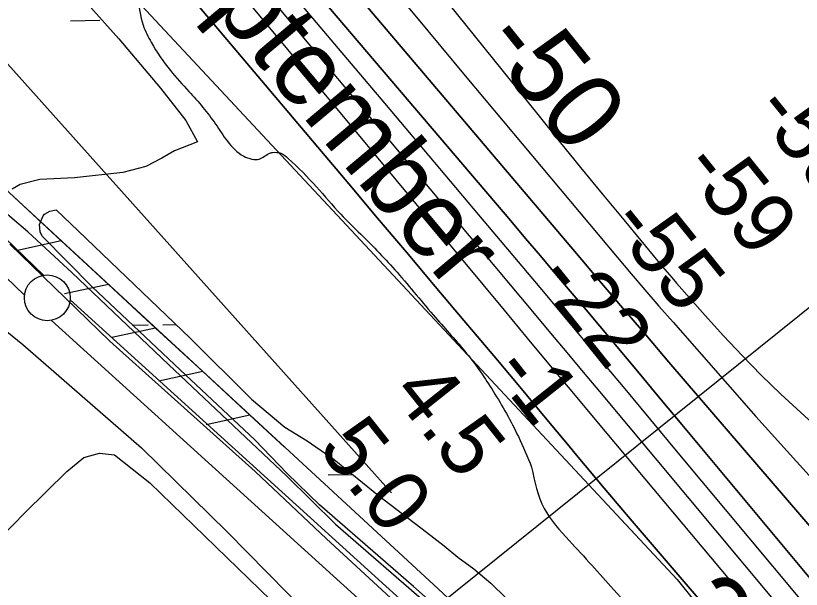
# Model space of a CAD drawing. Extents: x 3767014 to 3805179, y 361544 to 387384.
# Drawn here: x 3778084 to 3778940, y 382515 to 383140 of the extents above; entities that cross this region are included whole.
import ezdxf

# ---------------------------------------------------------------- set-up
doc = ezdxf.new("R2010")
doc.units = 0
for name, color, linetype in [('V-FLOD-BASE', 7, 'Continuous'), ('V-LEVE-TOET', 7, 'Continuous'), ('V-RIVR-EDGE', 7, 'Continuous'), ('V-RIVR-IDEN', 7, 'Continuous'), ('V-RIVR-RANG', 7, 'Continuous'), ('V-ROAD-CNTR', 7, 'Continuous'), ('V-RRAP-FSHR', 7, 'Continuous'), ('V-SITE-VEGE', 7, 'Continuous'), ('V-SURV-LINE', 7, 'Continuous'), ('V-TOPO-DPTH', 7, 'Continuous'), ('V-TOPO-MAJR', 7, 'Continuous'), ('V-TOPO-MAJR-IDEN', 7, 'Continuous'), ('V-TOPO-MINR', 7, 'Continuous'), ('V-TOPO-WATR', 7, 'Continuous'), ('V-WETL-SWMP', 7, 'Continuous')]:
    doc.layers.add(name, color=color, linetype=linetype)

msp = doc.modelspace()

# ---------------------------------------------------------------- linework, layer by layer
at = {"layer": 'V-FLOD-BASE'}
for points in [[(3778077.741, 382890.782), (3778186.756, 382785.16), (3778246.473, 382731.277)], [(3778692.098, 382328.079), (3778643.187, 382372.197), (3778588.09, 382420.374), (3778515.771, 382484.163), (3778422.761, 382569.696), (3778344.896, 382643.025), (3778246.473, 382731.277)]]:
    msp.add_lwpolyline(points, dxfattribs=at)
at = {"layer": 'V-LEVE-TOET'}
for points in [[(3778250.643, 382759.624), (3778145.759, 382859.539), (3778097.149, 382904.364), (3778080.063, 382918.624), (3778064.267, 382932.227), (3777948.815, 383043.517), (3777778.188, 383213.378), (3777627.559, 383359.319), (3777462.353, 383514.84), (3777284.081, 383693.815), (3777144.463, 383837.042), (3777009.432, 383982.073), (3776900.155, 384104.426), (3776770.729, 384259.935), (3776630.773, 384424.51), (3776502.622, 384572.538), (3776386.199, 384708.629), (3776267.407, 384848.723), (3776139.229, 384998.481), (3776021.579, 385139.17), (3775958.368, 385214.876)], [(3776800.942, 384059.618), (3776917.198, 383933.912), (3777056.954, 383782.03), (3777197.989, 383622.088), (3777340.366, 383486.983), (3777477.99, 383360.462), (3777641.365, 383211.261), (3777790.195, 383069.332), (3777927.911, 382937.04), (3778011.109, 382858.134), (3778016.915, 382847.329), (3778035.705, 382826.849), (3778091.825, 382781.568), (3778221.152, 382668.764), (3778314.358, 382577.321)], [(3778250.643, 382759.624), (3778379.499, 382638.087), (3778432.575, 382585.789), (3778534.504, 382496.902), (3778675.011, 382372.713), (3778703.947, 382346.241), (3778725.994, 382325.876)], [(3778314.358, 382577.321), (3778401.918, 382488.327), (3778454.988, 382436.713), (3778531.485, 382363.374), (3778603.096, 382303.001)]]:
    msp.add_lwpolyline(points, dxfattribs=at)
at = {"layer": 'V-RIVR-EDGE'}
for points in [[(3776564.722, 385223.299), (3776600.731, 385181.098), (3776661.2, 385105.736), (3776715.203, 385032.007), (3776816.784, 384902.358), (3776846.605, 384861.038), (3776857.883, 384843.218), (3776882.888, 384816.468), (3776915.962, 384782.419), (3776954.66, 384732.99), (3776978.836, 384698.155), (3777017.529, 384647.108), (3777120.713, 384511.794), (3777150.55, 384476.944), (3777181.198, 384442.901), (3777207.8, 384408.06), (3777254.587, 384359.42), (3777285.235, 384325.377), (3777306.975, 384286.503), (3777352.136, 384234.632), (3777398.919, 384184.375), (3777453.759, 384121.966), (3777499.732, 384071.711), (3777554.576, 384010.92), (3777589.252, 383970.397), (3777621.507, 383932.306), (3777678.778, 383871.509), (3777722.335, 383825.304), (3777756.204, 383785.592), (3777794.915, 383741.824), (3777871.521, 383651.056), (3777927.937, 383571.66), (3777966.622, 383517.378), (3777996.431, 383471.207), (3778029.475, 383425.027), (3778067.358, 383373.174), (3778126.177, 383284.876), (3778156.015, 383250.026), (3778180.211, 383223.278), (3778202.787, 383195.725), (3778212.458, 383181.952), (3778217.257, 383160.105), (3778222.842, 383129.359), (3778231.692, 383110.736), (3778252.643, 383079.952), (3778272.805, 383057.257), (3778301.832, 383021.601), (3778314.725, 383002.968), (3778332.478, 382986.749), (3778341.366, 382983.492), (3778349.453, 382983.472), (3778360.791, 382989.914), (3778364.028, 382990.715), (3778372.922, 382989.884), (3778380.996, 382984.203), (3778411.652, 382953.395), (3778438.266, 382923.406), (3778460.048, 382901.516), (3778499.574, 382860.173), (3778541.506, 382810.736), (3778575.377, 382771.833), (3778604.389, 382730.515), (3778631.764, 382681.114), (3778646.24, 382647.92)], [(3778646.24, 382647.92), (3778659.876, 382602.597), (3778687.287, 382567.754), (3778735.679, 382514.257), (3778796.164, 382445.365), (3778835.674, 382397.551), (3778888.899, 382335.956), (3778952.607, 382262.203), (3779012.275, 382190.077), (3779057.436, 382138.206), (3779100.988, 382089.574), (3779134.849, 382046.627), (3779162.264, 382013.401), (3779205.838, 381973.665), (3779260.7, 381920.153), (3779294.566, 381879.632), (3779325.194, 381837.502), (3779360.663, 381790.507), (3779412.312, 381745.899), (3779454.294, 381716.68), (3779488.994, 381685.863), (3779533.368, 381642.89), (3779576.119, 381597.495), (3779620.485, 381551.287), (3779676.969, 381499.388), (3779726.99, 381450.74), (3779776.179, 381392.389), (3779876.993, 381279.725), (3779935.05, 381210.029), (3779960.041, 381177.618), (3780000.375, 381136.273), (3780060.096, 381085.174), (3780089.114, 381046.283), (3780155.269, 380980.612), (3780221.433, 380918.984), (3780269.028, 380870.342), (3780345.672, 380794.939), (3780399.741, 380747.899), (3780525.62, 380632.747), (3780574.841, 380587.335), (3780617.604, 380546.793), (3780649.066, 380515.174), (3780673.232, 380476.295), (3780710.32, 380430.105), (3780715.929, 380409.064), (3780730.431, 380386.383), (3780746.557, 380366.934), (3780778.851, 380344.209), (3780832.137, 380307.684), (3780871.695, 380279.28), (3780938.666, 380216.842), (3780975.778, 380180.357), (3781018.547, 380142.24), (3781081.494, 380087.899), (3781142.025, 380037.607), (3781200.156, 379997.835), (3781279.276, 379942.646), (3781347.092, 379894.762), (3781401.179, 379855), (3781466.567, 379806.314), (3781540.856, 379760.032), (3781563.475, 379749.463), (3781591.761, 379741.305), (3781611.132, 379725.891), (3781641.814, 379705.597), (3781703.987, 379665.006), (3781768.578, 379621.175), (3781821.047, 379581.417), (3781840.409, 379561.959), (3781862.209, 379547.348), (3781884.029, 379540.824), (3781913.115, 379529.43), (3781965.635, 379509.89), (3782018.949, 379484.687), (3782023.776, 379474.162), (3782024.562, 379465.264), (3782031.018, 379459.587), (3782040.723, 379459.563), (3782056.888, 379455.479), (3782096.48, 379440.824), (3782142.534, 379422.918), (3782192.615, 379398.532), (3782256.437, 379370.877), (3782308.124, 379341.634), (3782355.768, 379312.402), (3782425.225, 379274.219), (3782483.37, 379240.108), (3782518.081, 379214.143), (3782612.541, 379148.401), (3782677.126, 379102.144), (3782722.345, 379073.726), (3782774.821, 379036.394), (3782813.562, 379004.757), (3782852.3, 378971.503), (3782891.856, 378942.291), (3782929.816, 378921.979), (3782948.387, 378909.802), (3782956.456, 378902.503), (3782965.324, 378891.159), (3782976.623, 378881.426), (3783009.747, 378867.595), (3783020.246, 378861.908), (3783062.243, 378838.351), (3783100.998, 378812.375), (3783151.876, 378783.135), (3783202.741, 378748.233), (3783247.956, 378718.198), (3783325.482, 378672.717), (3783407.843, 378619.945), (3783473.245, 378576.92), (3783515.225, 378546.893), (3783550.759, 378526.587), (3783593.566, 378503.836), (3783636.355, 378473.807), (3783701.749, 378427.547), (3783745.35, 378399.134), (3783781.695, 378379.634), (3783840.643, 378343.095), (3783916.53, 378288.722), (3783971.442, 378255.428), (3784058.669, 378208.305), (3784177.383, 378139.269), (3784249.255, 378096.228), (3784300.952, 378071.029), (3784367.999, 378039.322), (3784407.569, 378015.771), (3784474.592, 377974.36), (3784555.345, 377925.636), (3784594.113, 377904.513), (3784636.123, 377886.616), (3784690.236, 377857.368), (3784719.292, 377833.843), (3784772.601, 377806.214), (3784811.368, 377785.091), (3784863.85, 377750.185), (3784995.456, 377661.707), (3785050.364, 377626.795), (3785102.863, 377599.168), (3785153.772, 377582.059), (3785203.053, 377560.91), (3785266.865, 377529.211)]]:
    msp.add_spline(points, degree=3, dxfattribs=at)
at = {"layer": 'V-RIVR-RANG'}
msp.add_line((3778518.464, 382476.514), (3779220.036, 383040.248), dxfattribs=at)
at = {"layer": 'V-ROAD-CNTR'}
msp.add_arc((3779253.341, 383526.65), 1823.751, 212.363325, 236.331483, dxfattribs=at)
at = {"layer": 'V-RRAP-FSHR'}
for p, q in [((3778133.64, 382894.426), (3778085.925, 382884.046)), ((3778185.06, 382846.931), (3778137.346, 382836.551)), ((3778236.481, 382799.436), (3778188.766, 382789.056)), ((3778287.902, 382751.941), (3778240.187, 382741.561)), ((3778339.322, 382704.446), (3778291.608, 382694.066))]:
    msp.add_line(p, q, dxfattribs=at)
for points in [[(3782184.756, 379271.949), (3781634.784, 379600.702), (3781303.145, 379780.78), (3781133.821, 379909.411), (3780890.404, 380113.256), (3780565.67, 380378.863), (3780204.676, 380695.617), (3779970.329, 380928.932), (3779684.372, 381135.741), (3779561.421, 381256.633), (3779323.818, 381551.992), (3779094.739, 381872.997), (3778954.725, 382074.421), (3778782.34, 382292.407), (3778544.366, 382515.056), (3778048.414, 382973.145), (3777558.565, 383445.969), (3777072.653, 383926.093), (3776661.747, 384415.936), (3776254.152, 384895.528), (3775977.183, 385214.815)], [(3777068.879, 384385.699), (3778804.838, 382525.57), (3779492.47, 381669.823), (3779587.876, 381548.643), (3779796.903, 381343.309), (3779998.867, 381129.354), (3780179.181, 380943.203), (3780223.637, 380900.07), (3780597.798, 380548.597), (3780675.78, 380460.512), (3780749.105, 380378.076), (3780977.321, 380170.04), (3781125.621, 380046.136), (3781247.143, 379955.707), (3781372.841, 379865.857), (3781588.295, 379714.948), (3781871.171, 379550.27), (3782261.845, 379357.404), (3782506.653, 379202.456), (3782967.84, 378875.243), (3783363.457, 378614.539), (3783723.393, 378389.37)], [(3778133.64, 382894.426), (3778082.218, 382941.921)], [(3778236.481, 382799.436), (3778185.06, 382846.931), (3778133.639, 382894.426)], [(3778287.902, 382751.941), (3778236.48, 382799.436)], [(3778376.619, 382669.997), (3778339.322, 382704.446), (3778287.901, 382751.941)]]:
    msp.add_lwpolyline(points, dxfattribs=at)
at = {"layer": 'V-SITE-VEGE'}
msp.add_lwpolyline([(3778306.017, 382279.906), (3778175.401, 382112.937), (3778168.825, 382109.06), (3778157.598, 382111.755), (3777933.645, 382316.61), (3777925.885, 382330.922), (3777920.837, 382345.235), (3777914.234, 382364.968), (3777912.276, 382383.154), (3777919.993, 382403.677), (3777972.93, 382474.181), (3778094.471, 382598.452), (3778139.936, 382643.033), (3778158.163, 382658.325), (3778175.399, 382663.216), (3778191.591, 382661.164), (3778230.165, 382630.608), (3778386.067, 382479.557), (3778399.014, 382463.604), (3778402.715, 382448.655), (3778397.419, 382418.562), (3778367.082, 382366.141)], close=True, dxfattribs=at)
at = {"layer": 'V-SURV-LINE'}
for points in [[(3777377.157, 383568.76), (3778114.52, 382856.998)], [(3778093.693, 382835.405), (3777356.329, 383547.168)], [(3778143.366, 382830.007), (3778702.45, 382322.94)], [(3778682.288, 382300.726), (3778123.204, 382807.792)]]:
    msp.add_lwpolyline(points, dxfattribs=at)
msp.add_circle((3778118.48, 382832.327), 25, dxfattribs=at)
at = {"layer": 'V-TOPO-DPTH'}
for points in [[(3779101.046, 382406.885), (3778795.842, 382762.398), (3778770.574, 382791.888), (3778745.344, 382821.409), (3778720.17, 382850.979), (3778695.034, 382880.581), (3778321.003, 383321.918), (3778305.202, 383340.568), (3778289.403, 383359.22), (3778273.61, 383377.877), (3778257.82, 383396.537), (3778228.189, 383431.562), (3778227.219, 383432.713), (3778226.251, 383433.866), (3778225.287, 383435.022), (3778224.326, 383436.18), (3778186.457, 383481.98), (3778166.579, 383506.054), (3778146.725, 383530.147), (3778126.903, 383554.267), (3778107.105, 383578.405), (3777658.425, 384126.202)], [(3779101.046, 382406.885), (3778795.842, 382762.398), (3778770.574, 382791.888), (3778745.344, 382821.409), (3778720.17, 382850.979), (3778695.034, 382880.581), (3778321.003, 383321.918), (3778305.202, 383340.568), (3778289.403, 383359.22), (3778273.61, 383377.877), (3778257.82, 383396.537), (3778228.189, 383431.562), (3778227.219, 383432.713), (3778226.251, 383433.866), (3778225.287, 383435.022), (3778224.326, 383436.18), (3778186.457, 383481.98), (3778166.579, 383506.054), (3778146.725, 383530.147), (3778126.903, 383554.267), (3778107.105, 383578.405), (3777658.425, 384126.202)], [(3777617.591, 384049.155), (3777918.651, 383687.627), (3777960.381, 383637.574), (3778002.149, 383587.552), (3778043.975, 383537.578), (3778085.838, 383487.637), (3778120.766, 383446.017), (3778145.196, 383416.91), (3778169.627, 383387.804), (3778194.06, 383358.7), (3778218.495, 383329.598), (3778248.763, 383293.552), (3778288.317, 383246.414), (3778327.849, 383199.258), (3778367.35, 383152.075), (3778406.829, 383104.875), (3778648.871, 382815.29), (3778666.673, 382793.993), (3778684.475, 382772.695), (3778702.279, 382751.399), (3778720.082, 382730.103), (3778909.421, 382503.635)], [(3777617.591, 384049.155), (3777918.651, 383687.627), (3777960.381, 383637.574), (3778002.149, 383587.552), (3778043.975, 383537.578), (3778085.838, 383487.637), (3778120.766, 383446.017), (3778145.196, 383416.91), (3778169.627, 383387.804), (3778194.06, 383358.7), (3778218.495, 383329.598), (3778248.763, 383293.552), (3778288.317, 383246.414), (3778327.849, 383199.258), (3778367.35, 383152.075), (3778406.829, 383104.875), (3778648.871, 382815.29), (3778666.673, 382793.993), (3778684.475, 382772.695), (3778702.279, 382751.399), (3778720.082, 382730.103), (3778909.421, 382503.635)], [(3777813.681, 384002.604), (3777882.309, 383919.181), (3777950.792, 383835.638), (3778019.056, 383751.917), (3778087.174, 383668.076), (3778216.769, 383508.144), (3778236.811, 383483.45), (3778256.879, 383458.777), (3778276.987, 383434.137), (3778297.121, 383409.518), (3778362.065, 383330.233), (3778414.791, 383266.071), (3778467.65, 383202.019), (3778520.71, 383138.134), (3778573.904, 383074.359), (3778739.468, 382876.495), (3778754.517, 382858.646), (3778769.656, 382840.874), (3778784.928, 382823.217), (3778800.289, 382805.636), (3778890.59, 382703.067), (3778951.86, 382634.911), (3779014.051, 382567.625), (3779077.624, 382501.642)], [(3777813.681, 384002.604), (3777882.309, 383919.181), (3777950.792, 383835.638), (3778019.056, 383751.917), (3778087.174, 383668.076), (3778216.769, 383508.144), (3778236.811, 383483.45), (3778256.879, 383458.777), (3778276.987, 383434.137), (3778297.121, 383409.518), (3778362.065, 383330.233), (3778414.791, 383266.071), (3778467.65, 383202.019), (3778520.71, 383138.134), (3778573.904, 383074.359), (3778739.468, 382876.495), (3778754.517, 382858.646), (3778769.656, 382840.874), (3778784.928, 382823.217), (3778800.289, 382805.636), (3778890.59, 382703.067), (3778951.86, 382634.911), (3779014.051, 382567.625), (3779077.624, 382501.642)], [(3779309.16, 382094.881), (3778809.915, 382694.298), (3778795.025, 382712.178), (3778780.136, 382730.06), (3778765.249, 382747.943), (3778750.364, 382765.828), (3778735.454, 382783.692), (3778720.511, 382801.528), (3778705.516, 382819.32), (3778690.488, 382837.085), (3778688.217, 382839.761), (3778672.024, 382858.838), (3778655.827, 382877.912), (3778639.622, 382896.979), (3778623.412, 382916.043), (3778223.977, 383385.607), (3778212.332, 383399.339), (3778200.715, 383413.095), (3778189.139, 383426.886), (3778177.592, 383440.701), (3777800.934, 383892.722), (3777769.55, 383930.457), (3777738.213, 383968.231)], [(3777738.213, 383968.231), (3777769.55, 383930.457), (3777800.934, 383892.722), (3778177.592, 383440.701), (3778189.139, 383426.886), (3778200.715, 383413.095), (3778212.332, 383399.339), (3778223.977, 383385.607), (3778623.412, 382916.043), (3778639.622, 382896.979), (3778655.827, 382877.912), (3778672.024, 382858.838), (3778688.217, 382839.761), (3778690.488, 382837.085), (3778705.516, 382819.32), (3778720.511, 382801.528), (3778735.454, 382783.692), (3778750.364, 382765.828), (3778765.249, 382747.943), (3778780.136, 382730.06), (3778795.025, 382712.178), (3778809.915, 382694.298), (3779309.16, 382094.881)], [(3779236.017, 382030.277), (3778816.638, 382517.638), (3778786.088, 382553.314), (3778755.654, 382589.088), (3778725.394, 382625.009), (3778695.25, 382661.028), (3778687.159, 382670.743), (3778661.12, 382701.956), (3778635.047, 382733.139), (3778608.922, 382764.279), (3778582.761, 382795.389), (3778572.456, 382807.623), (3778541.109, 382844.823), (3778509.753, 382882.014), (3778478.382, 382919.193), (3778447.002, 382956.365), (3778145.465, 383313.415)]]:
    msp.add_lwpolyline(points, dxfattribs=at)
at = {"layer": 'V-TOPO-MAJR'}
msp.add_lwpolyline([(3778302.779, 383466.781), (3778652.939, 383031.937), (3778676.214, 383003.147), (3778699.563, 382974.418), (3778723.024, 382945.779), (3778746.559, 382917.201), (3778783.822, 382872.13), (3778788.808, 382866.156), (3778793.831, 382860.214), (3778798.909, 382854.318), (3778804.023, 382848.454), (3778835.195, 382813.046), (3778855.14, 382790.996), (3778875.468, 382769.314), (3778896.371, 382748.187), (3778917.658, 382727.428), (3778939.473, 382707.222), (3779421.519, 382267.07)], dxfattribs=at)
at = {"layer": 'V-TOPO-MINR'}
for points in [[(3777658.425, 384126.202), (3778107.105, 383578.405), (3778126.903, 383554.267), (3778146.725, 383530.147), (3778166.579, 383506.054), (3778186.457, 383481.98), (3778224.326, 383436.18), (3778225.287, 383435.022), (3778226.251, 383433.866), (3778227.219, 383432.713), (3778228.189, 383431.562), (3778257.82, 383396.537), (3778273.61, 383377.877), (3778289.403, 383359.22), (3778305.202, 383340.568), (3778321.003, 383321.918), (3778695.034, 382880.581), (3778720.17, 382850.979), (3778745.344, 382821.409), (3778770.574, 382791.888), (3778795.842, 382762.398), (3779101.046, 382406.885)], [(3777036.49, 384114.005), (3777259.111, 383885.577), (3777271.61, 383872.92), (3777284.218, 383860.373), (3777296.99, 383847.994), (3777309.871, 383835.726), (3777453.331, 383700.877), (3777496.647, 383660.865), (3777540.416, 383621.363), (3777584.864, 383582.627), (3777629.766, 383544.402), (3777674.307, 383505.815), (3777717.916, 383466.237), (3777760.129, 383425.172), (3777801.41, 383383.115), (3777922.903, 383254.971), (3777940.978, 383235.743), (3777958.943, 383216.412), (3777976.743, 383196.929), (3777994.432, 383177.344), (3778493.58, 382619.94), (3778493.58, 382619.94)], [(3777617.591, 384049.155), (3777918.651, 383687.627), (3777960.381, 383637.574), (3778002.149, 383587.552), (3778043.975, 383537.578), (3778085.838, 383487.637), (3778120.766, 383446.017), (3778145.196, 383416.91), (3778169.627, 383387.804), (3778194.06, 383358.7), (3778218.495, 383329.598), (3778248.763, 383293.552), (3778288.317, 383246.414), (3778327.849, 383199.258), (3778367.35, 383152.075), (3778406.829, 383104.875), (3778648.871, 382815.29), (3778666.673, 382793.993), (3778684.475, 382772.695), (3778702.279, 382751.399), (3778720.082, 382730.103), (3778909.421, 382503.635)], [(3777614.536, 384017.906), (3778112.899, 383424.18), (3778119.761, 383416.009), (3778126.626, 383407.839), (3778133.495, 383399.673), (3778140.366, 383391.509), (3778151.537, 383378.244), (3778152.824, 383376.713), (3778154.11, 383375.181), (3778155.393, 383373.648), (3778156.676, 383372.113), (3778166.881, 383359.889), (3778173.262, 383352.239), (3778179.638, 383344.585), (3778186.009, 383336.926), (3778192.375, 383329.264), (3778616.181, 382818.754), (3778641.318, 382788.516), (3778666.484, 382758.301), (3778691.69, 382728.12), (3778716.925, 382697.962), (3779102.687, 382237.579)], [(3777813.681, 384002.604), (3777882.309, 383919.181), (3777950.792, 383835.638), (3778019.056, 383751.917), (3778087.174, 383668.076), (3778216.769, 383508.144), (3778236.811, 383483.45), (3778256.879, 383458.777), (3778276.987, 383434.137), (3778297.121, 383409.518), (3778362.065, 383330.233), (3778414.791, 383266.071), (3778467.65, 383202.019), (3778520.71, 383138.134), (3778573.904, 383074.359), (3778739.468, 382876.495), (3778754.517, 382858.646), (3778769.656, 382840.874), (3778784.928, 382823.217), (3778800.289, 382805.636), (3778890.59, 382703.067), (3778951.86, 382634.911), (3779014.051, 382567.625), (3779077.624, 382501.642)], [(3777738.213, 383968.231), (3777769.55, 383930.457), (3777800.934, 383892.722), (3778177.592, 383440.701), (3778189.139, 383426.886), (3778200.715, 383413.095), (3778212.332, 383399.339), (3778223.977, 383385.607), (3778623.412, 382916.043), (3778639.622, 382896.979), (3778655.827, 382877.912), (3778672.024, 382858.838), (3778688.217, 382839.761), (3778690.488, 382837.085), (3778705.516, 382819.32), (3778720.511, 382801.528), (3778735.454, 382783.692), (3778750.364, 382765.828), (3778765.249, 382747.943), (3778780.136, 382730.06), (3778795.025, 382712.178), (3778809.915, 382694.298), (3779309.16, 382094.881)], [(3778377.323, 383172.963), (3778431.584, 383108.71), (3778485.822, 383044.437), (3778540.026, 382980.137), (3778594.207, 382915.817), (3778658.986, 382838.875), (3778680.743, 382812.996), (3778702.477, 382787.098), (3778724.175, 382761.17), (3778745.849, 382735.222), (3778805.669, 382663.507), (3778857.24, 382601.689), (3778908.814, 382539.875), (3778960.396, 382478.067)]]:
    msp.add_lwpolyline(points, dxfattribs=at)
at = {"layer": 'V-TOPO-WATR'}
msp.add_lwpolyline([(3778145.465, 383313.415), (3778447.002, 382956.365), (3778478.382, 382919.193), (3778509.753, 382882.014), (3778541.109, 382844.823), (3778572.456, 382807.623), (3778582.761, 382795.389), (3778608.922, 382764.279), (3778635.047, 382733.139), (3778661.12, 382701.956), (3778687.159, 382670.743), (3778695.25, 382661.028), (3778725.394, 382625.009), (3778755.654, 382589.088), (3778786.088, 382553.314), (3778816.638, 382517.638), (3779236.017, 382030.277)], dxfattribs=at)
at = {"layer": 'V-WETL-SWMP'}
for p, q in [((3778162.514, 383152.221), (3778196.42, 383114.513)), ((3778143.754, 383134.283), (3778175.751, 383134.728)), ((3778196.42, 383114.513), (3778241.679, 383060.946)), ((3778241.679, 383060.946), (3778269.379, 383025.607)), ((3778269.379, 383025.607), (3778282.083, 383002.368)), ((3778282.083, 383002.368), (3778256.936, 382992.424)), ((3778256.936, 382992.424), (3778243.232, 382984.665)), ((3778243.232, 382984.665), (3778225.778, 382975.59)), ((3778225.778, 382975.59), (3778200.744, 382968.91)), ((3778148.043, 382963.049), (3778110.363, 382961.196)), ((3778200.744, 382968.91), (3778148.043, 382963.049)), ((3778089.079, 382955.832), (3778080.362, 382950.666)), ((3778110.363, 382961.196), (3778089.079, 382955.832)), ((3778211.423, 382802.522), (3778228.398, 382802.758)), ((3778244.396, 382802.98), (3778258.776, 382803.18)), ((3778424.597, 382639.295), (3778451.35, 382639.666))]:
    msp.add_line(p, q, dxfattribs=at)
msp.add_lwpolyline([(3778651.948, 382398.499), (3778517.632, 382517.941), (3778415.019, 382606.825), (3778379.87, 382640.78), (3778344.701, 382677.471), (3778263.093, 382753.687), (3778167.596, 382843.939), (3778113.044, 382899.635), (3778110.663, 382904.214), (3778109.958, 382912.283), (3778113.851, 382921.578), (3778115.555, 382923.337), (3778121.27, 382926.89), (3778128.175, 382928.153), (3778152.196, 382905.448), (3778274.086, 382788.488), (3778340.952, 382721.922), (3778377.444, 382691.398), (3778401.504, 382676.522), (3778431.077, 382656.212), (3778479.267, 382616.879), (3778531.567, 382576.892), (3778550.837, 382561.98), (3778565.981, 382549.775), (3778583.183, 382536.9), (3778601.774, 382521.299), (3778618.317, 382504.998)], dxfattribs=at)

# ---------------------------------------------------------------- texts
at = {"layer": 'V-RIVR-IDEN'}
for s, p in [('September', (3778208.709, 383253.359)), (' 2012', (3778770.326, 382511.338))]:
    msp.add_text(s, height=83, rotation=309.98913, dxfattribs=at).set_placement(p)
at = {"layer": 'V-RIVR-RANG'}
for s, rotation, p in [('-59', 308.809472, (3778885.689, 383036.309)), ('-59', 308.809472, (3778807.611, 382973.828)), ('-55', 308.809472, (3778728.375, 382912.787)), ('-22', 308.809472, (3778648.974, 382851.952)), ('-1', 308.528326, (3778601.513, 382751.681)), ('4.5', 308.528326, (3778492.216, 382728.409)), ('5.0', 308.528326, (3778412.331, 382668.198))]:
    msp.add_text(s, height=67, rotation=rotation, dxfattribs=at).set_placement(p)
at = {"layer": 'V-TOPO-MAJR-IDEN'}
msp.add_text('-50', height=83, rotation=308.842929, dxfattribs=at).set_placement((3778589.835, 383110.343))

doc.saveas('drawing.dxf')
